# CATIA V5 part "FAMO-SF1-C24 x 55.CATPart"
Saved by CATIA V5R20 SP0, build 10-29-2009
Part number: FAMO-SF1-C24 x 55
Definition: NONE
Nomenclature: FAMO-SF1-C24 x 55
Source: Unknown
Description: FAMO-SF1-C24 x 55
Bounding box of the stored display mesh (mm): x -32 to 23, y -22 to 22, z -22 to 22
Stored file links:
  C:\Users\Utente\Desktop\IO LAVORO\3D X SITO CF\X SITO\FAMO\FAMO-SF1-C24 x 55.CATPart

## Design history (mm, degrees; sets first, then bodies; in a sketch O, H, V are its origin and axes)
Body1 "FAMO-SF1-C24 x 55" (main body)
  Solid1: solid without history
